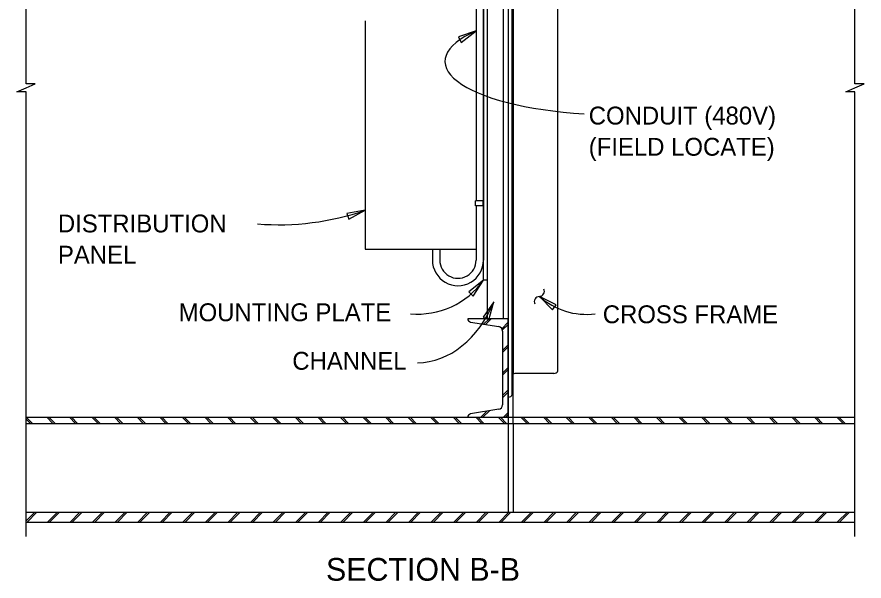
# Model space of a CAD drawing. Extents: x 927736.2 to 927809.6, y 636703.6 to 636757.7.
# Drawn here: x 927786.14 to 927803.81, y 636736.85 to 636748.62 of the extents above; entities that cross this region are included whole.
import ezdxf

# ---------------------------------------------------------------- set-up
doc = ezdxf.new("R2010")
doc.units = 0
for name, color, linetype in [('Default', 7, 'Continuous'), ('DimLines_dp', 7, 'Continuous'), ('Miscellaneous1', 7, 'Continuous'), ('Miscellaneous3', 7, 'Continuous')]:
    doc.layers.add(name, color=color, linetype=linetype)

msp = doc.modelspace()

# ---------------------------------------------------------------- linework, layer by layer
at = {"layer": 'Default'}
msp.add_line((927795.875, 636749.822), (927795.875, 636743.545), dxfattribs=at)
at = {"layer": 'DimLines_dp'}
for points in [[(927786.333, 636737.782), (927786.333, 636747.055), (927786.142, 636747.055), (927786.333, 636747.139), (927786.524, 636747.222), (927786.333, 636747.222), (927786.333, 636756.484)], [(927803.622, 636737.782), (927803.622, 636747.055), (927803.431, 636747.055), (927803.622, 636747.139), (927803.813, 636747.222), (927803.622, 636747.222), (927803.622, 636749.203)]]:
    msp.add_lwpolyline(points, dxfattribs=at)
for points in [[(927795.721, 636748.326), (927795.351, 636748.201), (927795.412, 636748.086)], [(927793.408, 636744.584), (927793.023, 636744.52), (927793.065, 636744.397)], [(927795.875, 636743.124), (927795.566, 636742.885), (927795.662, 636742.796)], [(927796.091, 636742.677), (927795.867, 636742.356), (927795.985, 636742.3)], [(927797.041, 636742.789), (927797.312, 636742.507), (927797.389, 636742.612)]]:
    msp.add_lwpolyline(points, close=True, dxfattribs=at)
for centre, radius, start, end in [((927791.608, 636749.822), 5.539, 265.3641, 288.9731), ((927794.495, 636744.121), 1.702, 265.0985, 324.1488), ((927797.035, 636742.898), 0.11, 272.3583, 24.0855), ((927797.044, 636742.677), 0.11, 92.3583, 204.0855), ((927798.022, 636743.886), 1.472, 228.179, 277.0931)]:
    msp.add_arc(centre, radius, start, end, dxfattribs=at)
for centre, major_axis, ratio, start_param, end_param in [((927798.697, 636747.688), (3.627, 0), 0.307602, 2.532927, 4.511363), ((927794.459, 636743.844), (-0.036, 2.438), 0.759061, 3.141594, 4.201813)]:
    msp.add_ellipse(centre, major_axis=major_axis, ratio=ratio, start_param=start_param, end_param=end_param, dxfattribs=at)
at = {"layer": 'Miscellaneous1'}
for p, q in [((927795.721, 636749.485), (927795.721, 636744.78)), ((927795.721, 636744.677), (927795.721, 636743.545)), ((927794.808, 636743.771), (927794.808, 636743.545)), ((927794.962, 636743.771), (927794.962, 636743.545))]:
    msp.add_line(p, q, dxfattribs=at)
for points in [[(927795.875, 636743.771), (927795.875, 636750.493), (927793.408, 636750.493), (927793.408, 636750.124)], [(927793.408, 636748.533), (927793.408, 636743.771), (927795.721, 636743.771)]]:
    msp.add_lwpolyline(points, dxfattribs=at)
for radius in [0.533, 0.379]:
    msp.add_arc((927795.342, 636743.545), radius, 180, 0.008, dxfattribs=at)
at = {"layer": 'Miscellaneous3'}
for p, q in [((927796.286, 636753.27), (927796.286, 636742.324)), ((927796.492, 636753.237), (927796.492, 636741.164)), ((927797.417, 636753.237), (927797.417, 636741.222)), ((927796.466, 636752.744), (927796.466, 636740.73)), ((927796.389, 636752.319), (927796.389, 636740.268)), ((927795.875, 636744.78), (927795.708, 636744.78)), ((927795.708, 636744.677), (927795.708, 636744.78)), ((927795.862, 636744.78), (927795.862, 636744.677)), ((927795.875, 636744.677), (927795.708, 636744.677)), ((927795.952, 636743.124), (927795.952, 636742.324)), ((927796.389, 636742.324), (927795.546, 636742.324)), ((927795.55, 636742.31), (927795.564, 636742.324)), ((927795.877, 636742.21), (927795.992, 636742.324)), ((927795.915, 636742.203), (927796.035, 636742.324)), ((927796.389, 636740.268), (927796.389, 636742.324)), ((927795.605, 636742.254), (927796.193, 636742.158)), ((927796.254, 636742.115), (927796.389, 636742.25)), ((927796.267, 636742.085), (927796.389, 636742.206)), ((927796.271, 636742.067), (927796.271, 636740.525)), ((927796.271, 636741.661), (927796.389, 636741.779)), ((927796.271, 636741.617), (927796.389, 636741.735)), ((927796.271, 636741.19), (927796.389, 636741.308)), ((927796.271, 636741.146), (927796.389, 636741.265)), ((927796.492, 636740.268), (927796.492, 636741.164)), ((927797.339, 636741.182), (927796.569, 636741.182)), ((927796.271, 636740.719), (927796.389, 636740.837)), ((927796.271, 636740.675), (927796.389, 636740.794)), ((927796.193, 636740.434), (927795.605, 636740.338)), ((927795.82, 636740.268), (927795.945, 636740.393)), ((927795.863, 636740.268), (927795.997, 636740.402)), ((927796.291, 636740.268), (927796.389, 636740.366)), ((927786.333, 636740.268), (927803.622, 636740.268)), ((927786.422, 636740.14), (927786.333, 636740.229)), ((927786.465, 636740.14), (927786.337, 636740.268)), ((927786.893, 636740.14), (927786.764, 636740.268)), ((927786.936, 636740.14), (927786.808, 636740.268)), ((927787.364, 636740.14), (927787.235, 636740.268)), ((927787.407, 636740.14), (927787.279, 636740.268)), ((927787.834, 636740.14), (927787.706, 636740.268)), ((927787.878, 636740.14), (927787.749, 636740.268)), ((927788.305, 636740.14), (927788.177, 636740.268)), ((927788.349, 636740.14), (927788.22, 636740.268)), ((927788.776, 636740.14), (927788.648, 636740.268)), ((927788.82, 636740.14), (927788.691, 636740.268)), ((927789.247, 636740.14), (927789.119, 636740.268)), ((927789.291, 636740.14), (927789.162, 636740.268)), ((927789.718, 636740.14), (927789.59, 636740.268)), ((927789.762, 636740.14), (927789.633, 636740.268)), ((927790.189, 636740.14), (927790.061, 636740.268)), ((927790.233, 636740.14), (927790.104, 636740.268)), ((927790.66, 636740.14), (927790.531, 636740.268)), ((927790.704, 636740.14), (927790.575, 636740.268)), ((927791.131, 636740.14), (927791.002, 636740.268)), ((927791.175, 636740.14), (927791.046, 636740.268)), ((927791.602, 636740.14), (927791.473, 636740.268)), ((927791.646, 636740.14), (927791.517, 636740.268)), ((927792.073, 636740.14), (927791.944, 636740.268)), ((927792.116, 636740.14), (927791.988, 636740.268)), ((927792.544, 636740.14), (927792.415, 636740.268)), ((927792.587, 636740.14), (927792.459, 636740.268)), ((927793.015, 636740.14), (927792.886, 636740.268)), ((927793.058, 636740.14), (927792.93, 636740.268)), ((927793.486, 636740.14), (927793.357, 636740.268)), ((927793.529, 636740.14), (927793.401, 636740.268)), ((927793.957, 636740.14), (927793.828, 636740.268)), ((927794, 636740.14), (927793.872, 636740.268)), ((927794.428, 636740.14), (927794.299, 636740.268)), ((927794.471, 636740.14), (927794.343, 636740.268)), ((927794.898, 636740.14), (927794.77, 636740.268)), ((927794.942, 636740.14), (927794.813, 636740.268)), ((927795.369, 636740.14), (927795.241, 636740.268)), ((927795.413, 636740.14), (927795.284, 636740.268)), ((927795.546, 636740.268), (927796.389, 636740.268)), ((927795.84, 636740.14), (927795.712, 636740.268)), ((927795.884, 636740.14), (927795.755, 636740.268)), ((927796.311, 636740.14), (927796.183, 636740.268)), ((927796.355, 636740.14), (927796.226, 636740.268)), ((927796.334, 636740.268), (927796.389, 636740.323)), ((927796.389, 636740.268), (927796.389, 636740.14)), ((927796.492, 636740.14), (927796.492, 636740.268)), ((927796.782, 636740.14), (927796.654, 636740.268)), ((927796.826, 636740.14), (927796.697, 636740.268)), ((927797.253, 636740.14), (927797.125, 636740.268)), ((927797.297, 636740.14), (927797.168, 636740.268)), ((927797.724, 636740.14), (927797.595, 636740.268)), ((927797.768, 636740.14), (927797.639, 636740.268)), ((927798.195, 636740.14), (927798.066, 636740.268)), ((927798.239, 636740.14), (927798.11, 636740.268)), ((927798.666, 636740.14), (927798.537, 636740.268)), ((927798.71, 636740.14), (927798.581, 636740.268)), ((927799.137, 636740.14), (927799.008, 636740.268)), ((927799.18, 636740.14), (927799.052, 636740.268)), ((927799.608, 636740.14), (927799.479, 636740.268)), ((927799.651, 636740.14), (927799.523, 636740.268)), ((927800.079, 636740.14), (927799.95, 636740.268)), ((927800.122, 636740.14), (927799.994, 636740.268)), ((927800.55, 636740.14), (927800.421, 636740.268)), ((927800.593, 636740.14), (927800.465, 636740.268)), ((927801.021, 636740.14), (927800.892, 636740.268)), ((927801.064, 636740.14), (927800.936, 636740.268)), ((927801.492, 636740.14), (927801.363, 636740.268)), ((927801.535, 636740.14), (927801.407, 636740.268)), ((927801.962, 636740.14), (927801.834, 636740.268)), ((927802.006, 636740.14), (927801.878, 636740.268)), ((927802.433, 636740.14), (927802.305, 636740.268)), ((927802.477, 636740.14), (927802.348, 636740.268)), ((927802.904, 636740.14), (927802.776, 636740.268)), ((927802.948, 636740.14), (927802.819, 636740.268)), ((927803.375, 636740.14), (927803.247, 636740.268)), ((927803.419, 636740.14), (927803.29, 636740.268)), ((927786.333, 636740.14), (927803.622, 636740.14)), ((927796.389, 636740.14), (927796.389, 636738.29)), ((927796.492, 636740.14), (927796.492, 636738.29)), ((927786.333, 636738.29), (927803.622, 636738.29)), ((927786.333, 636738.109), (927786.514, 636738.29)), ((927786.352, 636738.084), (927786.557, 636738.29)), ((927786.779, 636738.084), (927786.985, 636738.29)), ((927786.823, 636738.084), (927787.028, 636738.29)), ((927787.25, 636738.084), (927787.456, 636738.29)), ((927787.294, 636738.084), (927787.499, 636738.29)), ((927787.721, 636738.084), (927787.926, 636738.29)), ((927787.765, 636738.084), (927787.97, 636738.29)), ((927788.192, 636738.084), (927788.397, 636738.29)), ((927788.236, 636738.084), (927788.441, 636738.29)), ((927788.663, 636738.084), (927788.868, 636738.29)), ((927788.707, 636738.084), (927788.912, 636738.29)), ((927789.134, 636738.084), (927789.339, 636738.29)), ((927789.177, 636738.084), (927789.383, 636738.29)), ((927789.605, 636738.084), (927789.81, 636738.29)), ((927789.648, 636738.084), (927789.854, 636738.29)), ((927790.076, 636738.084), (927790.281, 636738.29)), ((927790.119, 636738.084), (927790.325, 636738.29)), ((927790.547, 636738.084), (927790.752, 636738.29)), ((927790.59, 636738.084), (927790.796, 636738.29)), ((927791.018, 636738.084), (927791.223, 636738.29)), ((927791.061, 636738.084), (927791.267, 636738.29)), ((927791.489, 636738.084), (927791.694, 636738.29)), ((927791.532, 636738.084), (927791.738, 636738.29)), ((927791.959, 636738.084), (927792.165, 636738.29)), ((927792.003, 636738.084), (927792.208, 636738.29)), ((927792.43, 636738.084), (927792.636, 636738.29)), ((927792.474, 636738.084), (927792.679, 636738.29)), ((927792.901, 636738.084), (927793.107, 636738.29)), ((927792.945, 636738.084), (927793.15, 636738.29)), ((927793.372, 636738.084), (927793.578, 636738.29)), ((927793.416, 636738.084), (927793.621, 636738.29)), ((927793.843, 636738.084), (927794.049, 636738.29)), ((927793.887, 636738.084), (927794.092, 636738.29)), ((927794.314, 636738.084), (927794.52, 636738.29)), ((927794.358, 636738.084), (927794.563, 636738.29)), ((927794.785, 636738.084), (927794.99, 636738.29)), ((927794.829, 636738.084), (927795.034, 636738.29)), ((927795.256, 636738.084), (927795.461, 636738.29)), ((927795.3, 636738.084), (927795.505, 636738.29)), ((927795.727, 636738.084), (927795.932, 636738.29)), ((927795.771, 636738.084), (927795.976, 636738.29)), ((927796.198, 636738.084), (927796.403, 636738.29)), ((927796.241, 636738.084), (927796.447, 636738.29)), ((927796.669, 636738.084), (927796.874, 636738.29)), ((927796.712, 636738.084), (927796.918, 636738.29)), ((927797.14, 636738.084), (927797.345, 636738.29)), ((927797.183, 636738.084), (927797.389, 636738.29)), ((927797.611, 636738.084), (927797.816, 636738.29)), ((927797.654, 636738.084), (927797.86, 636738.29)), ((927798.082, 636738.084), (927798.287, 636738.29)), ((927798.125, 636738.084), (927798.331, 636738.29)), ((927798.553, 636738.084), (927798.758, 636738.29)), ((927798.596, 636738.084), (927798.802, 636738.29)), ((927799.023, 636738.084), (927799.229, 636738.29)), ((927799.067, 636738.084), (927799.272, 636738.29)), ((927799.494, 636738.084), (927799.7, 636738.29)), ((927799.538, 636738.084), (927799.743, 636738.29)), ((927799.965, 636738.084), (927800.171, 636738.29)), ((927800.009, 636738.084), (927800.214, 636738.29)), ((927800.436, 636738.084), (927800.642, 636738.29)), ((927800.48, 636738.084), (927800.685, 636738.29)), ((927800.907, 636738.084), (927801.113, 636738.29)), ((927800.951, 636738.084), (927801.156, 636738.29)), ((927801.378, 636738.084), (927801.584, 636738.29)), ((927801.422, 636738.084), (927801.627, 636738.29)), ((927801.849, 636738.084), (927802.055, 636738.29)), ((927801.893, 636738.084), (927802.098, 636738.29)), ((927802.32, 636738.085), (927802.525, 636738.29)), ((927802.364, 636738.085), (927802.569, 636738.29)), ((927802.791, 636738.085), (927802.996, 636738.29)), ((927802.835, 636738.085), (927803.04, 636738.29)), ((927803.262, 636738.085), (927803.467, 636738.29)), ((927803.306, 636738.085), (927803.511, 636738.29)), ((927786.333, 636738.084), (927803.622, 636738.084))]:
    msp.add_line(p, q, dxfattribs=at)
msp.add_lwpolyline([(927795.875, 636751.141), (927795.952, 636751.141), (927795.952, 636743.124), (927795.875, 636743.124)], close=True, dxfattribs=at)
for centre, radius, start, end in [((927795.617, 636742.324), 0.0705, 180, 260.5), ((927796.178, 636742.067), 0.0925, 360, 80.5), ((927796.178, 636740.525), 0.0925, 279.5, 360), ((927795.617, 636740.268), 0.0705, 99.5, 180)]:
    msp.add_arc(centre, radius, start, end, dxfattribs=at)
for centre, major_axis, end_param in [((927796.569, 636741.129), (-0.103, 0), 6.283185), ((927797.339, 636741.222), (0.0771, 0), 6.283185), ((927796.389, 636740.73), (0.0771, 0), 6.270045)]:
    msp.add_ellipse(centre, major_axis=major_axis, ratio=0.5176, start_param=4.712389, end_param=end_param, dxfattribs=at)

# ---------------------------------------------------------------- texts
at = {"layer": 'Default'}
msp.add_text('SECTION B-B', height=0.4736, dxfattribs=at).set_placement((927792.589, 636736.86))
at = {"layer": 'DimLines_dp'}
for s, height, p in [('CONDUIT (480V)', 0.37296, (927798.07, 636746.373)), ('(FIELD LOCATE)', 0.37296, (927798.07, 636745.722)), ('DISTRIBUTION ', 0.37296, (927786.996, 636744.123)), ('PANEL', 0.373, (927786.996, 636743.471)), ('MOUNTING PLATE', 0.37296, (927789.516, 636742.271)), ('CROSS FRAME', 0.37296, (927798.363, 636742.229)), ('CHANNEL', 0.373, (927791.886, 636741.259))]:
    msp.add_text(s, height=height, dxfattribs=at).set_placement(p)

doc.saveas('drawing.dxf')
